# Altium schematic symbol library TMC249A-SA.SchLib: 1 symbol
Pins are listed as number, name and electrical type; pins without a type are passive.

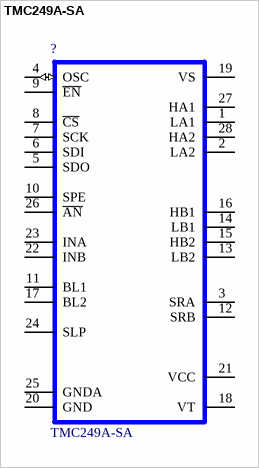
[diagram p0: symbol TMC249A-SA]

## TMC249A-SA
designator ?
High Current Microstep Stepper Motor Driver with sensorless stall detection, protection / diagnosis and SPI Interface, SO-28; Manufacturer: TRINAMIC; Geometry.Height: 2.65mm; Ordercode - Distri#1: 1460-10565-5-ND; Ordercode - Distri#2: 1214193
footprint TMC_SO28_SOT136-1_1.27_18X7.5
pins: 1 LA1, 2 LA2, 3 SRA, 4 OSC (io), 5 SDO, 6 SDI, 7 SCK, 8 ~{CS}, 9 ~{EN}, 10 SPE, 11 BL1, 12 SRB, 13 LB2, 14 LB1, 15 HB2, 16 HB1, 17 BL2, 18 VT (power), 19 VS (power), 20 GND, 21 VCC (power), 22 INB, 23 INA, 24 SLP, 25 GNDA, 26 ~{AN}, 27 HA1, 28 HA2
